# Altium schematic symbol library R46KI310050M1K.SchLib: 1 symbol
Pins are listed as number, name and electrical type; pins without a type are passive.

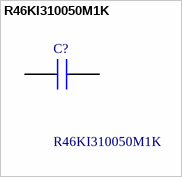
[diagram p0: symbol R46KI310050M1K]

## R46KI310050M1K
designator C?
R46 275 VAC, Film, Metallized Polypropylene, Safety, 0.1 uF, 10%, 275 VAC (X2), 560 VDC, 110C, 15mm; Manufacturer_Name: Yageo Group; Geometry.Height: 11.1mm
footprint R46KI310050M1K
pins: 1, 2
